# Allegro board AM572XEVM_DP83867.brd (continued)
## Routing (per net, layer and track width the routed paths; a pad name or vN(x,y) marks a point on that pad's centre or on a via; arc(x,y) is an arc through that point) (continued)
AM_CAP10: length 1.2
  TOP w0.12: U11.J16 v2(65.79,36.01)
  BOTTOM w0.254: C146.1 66.19,36.4 v2(65.79,36.01)
AM_CAP11: length 1.1
  TOP w0.12: U11.J10 v2(71.39,36.01)
  BOTTOM w0.254: C148.1 71.07,36.32 v2(71.39,36.01)
AM_CAP12: length 1.1
  TOP w0.12: U11.T20 v2(62.59,42.41)
  BOTTOM w0.254: v2(62.59,42.41) 62.9,42.09 C150.1
AM_CAP13: length 1.1
  TOP w0.12: U11.Y13 v2(68.99,45.61)
  BOTTOM w0.254: C152.1 68.67,45.29 v2(68.99,45.61)
AM_CAP14: length 2.5
  TOP w0.12: U11.K16 v2(66.59,37.61)
  BOTTOM w0.254: v2(66.59,37.61) 66.9,37.29 C154.1 67.56,36.54 R417.1
AUDIN_L: length 21.1
  TOP w0.102: v1(57.53,21.08) 57.67,20.94 U18.14
  INT_L3 w0.094: v1(44.83,12.7) 44.94,12.81 54.39,12.81 56.15,14.57 56.15,19.7 v1(57.53,21.08)
  BOTTOM w0.102: R230.1 v1(44.83,12.7)
AUDIN_R: length 21.2
  TOP w0.102: v1(56.77,21.08) 56.67,20.98 U18.16
  INT_L3 w0.094: v1(44.07,12.7) 44.58,13.21 54.23,13.21 55.75,14.73 55.75,19.8 56.77,20.81 v1(56.77,21.08)
  BOTTOM w0.102: R233.1 v1(44.07,12.7)
AUDIN_RL: length 1.6
  BOTTOM w0.12: C256.1 R233.2
AUDIN_RR: length 1.6
  BOTTOM w0.12: C255.1 R230.2
AUDIO_L: length 33.2
  TOP w0.102: U18.27 57.67,14.72 58.42,13.97 v1(58.42,13.72)
  BOTTOM w0.102: C250.1 32.26,12.7 31.93,13.03 31.93,13.39 33.55,15.01 50.53,15.01 52.81,12.73 57.05,12.73 58.04,13.72 v1(58.42,13.72)
AUDIO_R: length 33.1
  TOP w0.102: U18.29 58.67,14.48 v1(58.67,14.48)
  BOTTOM w0.102: v1(58.67,14.48) 58.3,14.48 56.9,13.08 52.96,13.08 50.67,15.37 33.41,15.37 31.57,13.53 31.57,13.03 31.24,12.7 C251.1
AUXFAN_EN: length 57.3
  TOP w0.12: U5.A12 v2(71.79,68.01)
  SIG_L5 w0.094: v1(81.41,58.39) 82.04,59.03 82.04,61.09 80.65,62.48 78.49,62.48 76.96,64.01 74.17,64.01 72.64,65.53 72.64,67.15 v2(71.79,68.01)
  BOTTOM w0.12: U32.1 110.49,50.8 109.86,51.44 85.34,51.44 82.3,54.48 82.3,57.51 v1(81.41,58.39) ; R24.1 74.84,67.98 74.68,67.82 71.98,67.82 v2(71.79,68.01)
B_UART3_RX: length 4.1
  TOP w0.12: U20.2 v1(27.3,37.08) 27.06,37.08 P10.4
  BOTTOM w0.12: R236.1 27.53,37.3 v1(27.3,37.08)
B_UART3_TX: length 2.8
  TOP w0.12: U20.3 27.06,36.58 P10.5
BATEN0: length 12.6
  TOP w0.12: v1(99.82,29.97) 99.06,30.73 99.06,34.54 98.26,35.34 R204.1 94.96,35.3 U17.36
  BOTTOM w0.12: v1(99.82,29.97) 100.08,29.72 100.08,28.56 100.2,28.44 U29.4
BATEN1: length 12
  TOP w0.12: v1(100.71,29.97) 100.33,29.59 100.33,29.58 100.21,29.46 99.57,29.46 98.81,30.23 98.81,34.42 98.17,35.05 95.58,35.05 95.46,34.93 U17.35
  BOTTOM w0.12: U29.5 100.71,28.99 v1(100.71,29.97)
BATEN2: length 4.8
  TOP w0.12: v1(97.16,34.54) 96.9,34.29 U17.33
  BOTTOM w0.12: U30.4 100.08,33.52 99.57,34.04 97.66,34.04 v1(97.16,34.54)
BATEN3: length 4.7
  TOP w0.12: U17.32 97.73,33.59 97.92,33.78 v1(97.92,34.54)
  BOTTOM w0.12: U30.5 100.22,34.02 99.7,34.54 v1(97.92,34.54)
BU_BATT: length 6.3
  TOP w0.12: BAT1.1 87.76,86.87 86.23,85.34 84.96,85.34 84.84,85.47 U6.3
  BOTTOM w0.12: R416.1 BAT1.1
CDC_CAP1: length 3
  TOP w0.12: C436.1 28.46,47.11 U7.19
CDC_CAP2: length 2.8
  TOP w0.12: C437.1 27.46,46.58 U7.17
CDC_OE: length 1.6
  TOP w0.12: U7.7 27.96,53.98 27.69,54.25 R313.1
CDC_OS1: length 5
  TOP w0.12: R310.2 R312.1 25.91,54.36 25.4,53.85 25.4,52.32 25.67,52.05 U7.10
CDC_OS2: length 4.1
  TOP w0.12: R311.1 R309.2 25.28,50.33 25.4,50.44 25.4,51.31 25.65,51.56 26.72,51.56 U7.11
CDC_OSCIN: length 3.4
  TOP w0.12: v1(29.97,47.5) 29.58,47.5 29.46,47.62 U7.21
  BOTTOM w0.12: Y8.3 29.97,46.35 v1(29.97,47.5) 30.01,47.53 C435.1
CLKOUT3: length 68.5
  TOP w0.12: U11.C23 v2(60.19,31.21)
  SIG_L5 w0.094: v1(29.21,32.13) 29.72,31.62 31.62,31.62 33.4,29.84 33.4,24.89 32.51,24 32.51,17.53 32.89,17.14 48.39,17.14 51.82,20.57 51.82,25.4 54.48,28.07 57.79,28.07 58.95,29.23 58.95,29.74 59.18,29.97 59.45,29.97 59.82,30.34 59.82,30.61 60.19,30.98 v2(60.19,31.21)
  BOTTOM w0.12: v1(29.21,32.13) 27.05,32.13 26.71,31.79 25.24,31.79 25.07,31.96 18.49,31.96 18.08,31.54 P17.41
CON.PCIE_RXN0: length 53.4
  TOP w0.12: U11.AG13 v3(68.99,51.21)
  BOTTOM w0.102: v3(68.99,51.21) 68.58,51.61 68.58,52.46 68.35,52.68 68.35,55.09 67.23,56.21 66.34,56.21 65.91,56.64 54.86,56.64 50.08,61.42 25.57,61.42 24.52,62.47 24.26,62.47 24.03,62.25 P19.25
CON.PCIE_RXN1: length 60.3
  TOP w0.12: U11.AG11 v3(70.59,51.21)
  BOTTOM w0.102: v3(70.59,51.21) 70.18,51.62 70.18,52.78 70.74,53.34 70.74,55.75 68.2,58.29 55.88,58.29 51.05,63.12 27.18,63.12 25.78,64.52 25.78,67.31 25.02,68.07 24.26,68.07 24.03,67.85 P19.18
CON.PCIE_RXP0: length 53.4
  TOP w0.12: U11.AH13 v3(68.99,52.01)
  BOTTOM w0.102: v3(68.99,52.01) 68.95,52.04 68.95,52.59 68.71,52.83 68.71,55.24 67.38,56.57 66.49,56.57 66.06,57 55.01,57 50.23,61.78 26.34,61.78 26.26,61.87 26.26,61.97 26.17,62.06 26.04,62.06 25.95,61.97 25.95,61.87 25.86,61.78 25.72,61.78 24.67,62.83 24.26,62.83 24.03,63.05 P19.24
CON.PCIE_RXP1: length 60.2
  TOP w0.12: U11.AH11 v3(70.59,52.01)
  BOTTOM w0.102: P19.17 24.06,68.65 24.28,68.43 25.17,68.43 26.14,67.46 26.14,64.66 26.3,64.5 26.42,64.5 26.49,64.57 26.62,64.57 26.71,64.48 26.71,64.35 26.64,64.29 26.64,64.16 27.33,63.47 51.2,63.47 56.03,58.65 68.35,58.65 71.09,55.9 71.09,53.19 70.53,52.63 70.53,52.06 v3(70.59,52.01)
CON.PCIE_TXN0: length 48
  BOTTOM w0.102: P19.28 24.03,59.85 24.26,60.07 24.77,60.07 25.27,60.58 49.66,60.58 54.36,55.88 65.71,55.88 66.06,55.52 66.65,55.52 67.08,55.1 67.08,54.35 C423.2
CON.PCIE_TXN1: length 52.5
  BOTTOM w0.102: P19.21 24.1,65.45 24.25,65.6 24.7,65.6 24.89,65.41 24.89,64.14 26.78,62.26 50.53,62.26 55.25,57.53 67.56,57.53 69.61,55.49 69.61,55.1 C425.2
CON.PCIE_TXP0: length 49.2
  BOTTOM w0.102: P19.27 24.03,60.65 24.26,60.43 24.62,60.43 24.78,60.59 24.78,60.72 24.59,60.91 24.59,61.04 24.68,61.13 24.8,61.13 25,60.93 49.81,60.93 54.5,56.24 65.85,56.24 66.21,55.88 66.8,55.88 67.44,55.24 67.44,54.32 C422.2
CON.PCIE_TXP1: length 53.2
  BOTTOM w0.102: C424.2 69.96,55.1 69.96,55.63 67.71,57.89 55.4,57.89 50.67,62.61 26.92,62.61 25.25,64.29 25.25,65.56 24.85,65.95 24.27,65.95 23.97,66.25 P19.20
CON_MMC1_CLK: length 22.6
  TOP w0.12: D21.3 69.61,13.62 R269.2 R262.2 67.83,12.29 69.39,10.72 v1(70.89,10.72)
  BOTTOM w0.12: v1(70.89,10.72) 70.89,11.25 70.46,11.68 69.6,11.68 69.19,11.28 69.19,10.24 69.82,9.6 69.82,8.46 70.1,8.18 70.89,8.18 71.27,7.8 71.27,6.93 71.12,6.78 70.66,6.78 70.56,6.68 70.56,6.4 70.69,6.27 71.15,6.27 71.27,6.15 71.27,5.89 71.15,5.77 70.36,5.77 70.15,5.56 70.15,5.33 70.38,5.11 70.71,5.11 70.92,4.9 P12.5
CON_MMC1_CMD: length 20.7
  TOP w0.12: D21.5 71.43,14.6 72.41,13.62 R267.2 R263.2 72.79,12.29 72.06,11.56 72.06,10.62 72.56,10.12 72.56,9.49 72.29,9.22 v1(69.22,9.22)
  BOTTOM w0.12: v1(69.22,9.22) 69.22,8.13 69.72,7.62 69.72,5.03 69.6,4.9 69.19,4.9 69.06,5.03 69.06,5.69 68.91,5.84 68.61,5.84 68.45,5.69 68.45,2.4 P12.3
CON_MMC1_DAT0: length 20.7
  TOP w0.12: R270.2 R261.2 66.47,12.29 66.04,11.85 66.04,10.19 66.2,10.02 D20.5 67,10.02 67.13,10.16 v1(71.37,10.16)
  BOTTOM w0.12: P12.7 73.12,4.13 71.83,5.41 71.83,5.69 72.09,5.94 72.62,5.94 72.82,6.15 72.82,6.45 72.59,6.68 72.03,6.68 71.83,6.88 71.83,8.1 71.37,8.56 70.82,8.56 70.51,8.86 70.51,9.86 70.82,10.16 v1(71.37,10.16)
CON_MMC1_DAT1: length 20.8
  TOP w0.12: R271.2 R260.2 65.21,12.27 65.1,12.27 64.69,11.86 64.69,9.22 64.89,9.03 D20.3 65.62,9.03 66.14,9.55 67.28,9.55 67.44,9.7 v1(71.91,9.7)
  BOTTOM w0.12: v1(71.91,9.7) 73.61,8 73.61,3.68 73.96,3.33 73.96,2.38 P12.8
CON_MMC1_DAT2: length 20.8
  TOP w0.12: v1(68.1,8.31) 74.24,8.31 74.78,8.84 74.78,9.38 D22.5 74.78,10.67 74.78,11.76 75.3,12.29 R265.2 R266.2
  BOTTOM w0.12: v1(68.1,8.31) 66.78,8.31 66.56,8.09 66.56,7.71 66.78,7.49 67.01,7.49 67.21,7.29 67.21,3.3 66.73,2.82 66.73,2.34 P12.1
CON_MMC1_DAT3: length 20.6
  TOP w0.12: v1(68.68,8.74) 73.79,8.74 D22.3 73.86,9.03 73.46,9.42 73.46,11.71 74.03,12.29 R264.2 R268.2
  BOTTOM w0.12: P12.2 67.62,2.9 67.77,3.05 67.77,5.97 68.05,6.25 69.06,6.25 69.22,6.4 69.22,6.58 69.06,6.73 68,6.73 67.77,6.96 67.77,7.59 67.92,7.75 68.38,7.75 68.68,8.05 v1(68.68,8.74)
CONN_SATA_RXN: length 7.8
  TOP w0.102: U33.12 79.24,87.37 v3(79.38,87.5)
  BOTTOM w0.102: v3(79.38,87.5) 79.38,87.71 79.45,87.78 79.45,93.12 79.16,93.41 79.16,93.97 C418.2
CONN_SATA_RXP: length 7.8
  TOP w0.102: v3(79.88,87.5) 79.74,87.36 U33.11
  BOTTOM w0.102: C420.2 79.51,93.97 79.51,93.56 79.81,93.27 79.81,87.78 79.88,87.71 v3(79.88,87.5)
CONN_SATA_TXN: length 1.4
  TOP w0.102: U33.14 78.24,87.37 v3(78.11,87.5)
  BOTTOM w0.102: C417.2 78.11,87.92 v3(78.11,87.5)
CONN_SATA_TXP: length 1.5
  TOP w0.102: U33.15 77.74,87.36 v3(77.6,87.5)
  BOTTOM w0.102: v3(77.6,87.5) 77.6,87.79 C416.1
CPU_NMIN: length 5.6
  TOP w0.12: U11.D21 v2(61.79,32.01)
  BOTTOM w0.12: R47.1 R46.2 60.33,29.08 60.59,29.34 60.59,31 61.6,32.01 v2(61.79,32.01)
CPU_POR_RESETN: length 81.7
  TOP w0.12: R53.2 v1(55.25,11.3)
  INT_L3 w0.094: v1(55.25,11.3) 56.26,11.3 57.02,12.06 60.02,12.06 63.25,8.84 65.18,8.84 66.45,10.11 68.68,10.11 69.67,11.1 69.67,11.13 70.61,12.06 75.31,12.06 77.47,14.22 77.47,24.38 78.99,25.91 78.99,45.72 78.66,46.05 78.41,46.05 77.34,47.12 77.34,47.37 77.09,47.62 76.84,47.62 76.58,47.88 76.58,49.15 75.82,49.91 75.82,59.56 76.82,60.57 v1(76.82,61.47) 76.33,61.96 v1(76.33,64.77)
  BOTTOM w0.12: v1(76.33,64.77) R41.2 ; U9.6 v1(76.82,61.47)
CPU_RESETN: length 83.5
  TOP w0.12: R55.1 v1(53.98,11.3)
  INT_L3 w0.094: v1(78.87,63.37) 78.74,63.25 78.74,60.96 79.25,60.45 79.25,58.67 78.74,58.17 78.74,52.58 79.5,51.82 79.5,48.77 79.99,48.28 79.99,31.35 79.25,30.61 79.25,25.65 77.72,24.13 77.72,13.97 75.56,11.81 71.04,11.81 69.01,9.78 66.8,9.78 65.51,8.48 62.99,8.48 59.66,11.81 57.28,11.81 56.26,10.79 54.48,10.79 v1(53.98,11.3)
  BOTTOM w0.12: R42.2 79.12,65.28 78.87,65.02 v1(78.87,63.37) 79.36,62.88 U10.1
DCAN1_RX: length 61.8
  TOP w0.12: U11.G19 v2(63.39,34.41)
  SIG_L10 w0.094: v2(63.39,34.41) 63.36,34.41 62.99,34.04 62.99,33.4 62.77,33.18 56.8,33.18 55.75,32.13 55.75,30.23 50.55,25.02 50.55,20.32 48.39,18.16 34.54,18.16 33.91,18.8 33.91,21.21 33.15,21.97 32.64,21.97 29.3,25.31 21.67,25.31 21.48,25.49 20.8,25.49 v1(20.45,25.14)
  BOTTOM w0.12: v1(20.45,25.14) 21.25,24.34 P17.20
DCAN1_TX: length 62.9
  TOP w0.12: U11.G20 v2(62.59,34.41)
  SIG_L10 w0.094: v2(62.59,34.41) 62.59,34.39 62.22,34.03 56.13,34.03 53.98,31.88 53.98,28.83 50.29,25.15 50.29,20.45 48.26,18.41 34.67,18.41 34.16,18.92 34.16,21.59 30.23,25.53 21.76,25.53 21.57,25.71 19.5,25.71 v1(18.92,25.14)
  BOTTOM w0.12: v1(18.92,25.14) 18.12,24.34 P17.50
DDR1_A0: length 51.4
  TOP w0.12: v2(37.78,47.21) U24.N3 ; v2(37.78,58.41) U23.N3 ; U11.AD20 v2(62.59,48.81)
  INT_L3 w0.094: v2(37.78,47.21) 37.38,47.61 37.38,54.65 38.61,55.88 38.61,57.09 37.78,57.91 v2(37.78,58.41)
  SIG_L5 w0.094: v2(62.59,48.81) 63,48.39 63.5,48.39 63.81,48.08 63.81,47.05 63.59,46.83 56.55,46.83 52.58,50.8 45.59,50.8 43.81,52.58 43.81,54.86 40.63,58.05 40.63,59.32 40.34,59.61 38.42,59.61 38.18,59.37 38.18,59.04 37.78,58.64 v2(37.78,58.41)
  BOTTOM w0.12: R364.1 v2(37.78,47.21)
DDR1_A1: length 51.4
  TOP w0.12: U11.AC19 v2(63.39,48.01) ; v2(36.98,43.21) U24.P7 ; v2(36.98,54.41) U23.P7
  SIG_L10 w0.094: v2(63.39,48.01) 63.39,48.23 63.76,48.61 63.76,51.43 63.61,51.58 63.23,51.58 62.99,51.82 62.99,53.21 58.55,57.66 38.1,57.66 36.45,56.01 36.45,54.94 v2(36.98,54.41) 36.58,54.01 36.58,52.52 37.03,52.07 37.03,49.66 36.58,49.21 36.58,46.81 37.03,46.35 37.03,44.39 36.58,43.94 36.58,43.61 v2(36.98,43.21)
  BOTTOM w0.12: R365.1 v2(36.98,43.21)
DDR1_A2: length 51.5
  TOP w0.12: U11.AC20 v2(62.59,48.01) ; v2(36.98,58.41) U23.P3 ; v2(36.98,47.21) U24.P3
  INT_L3 w0.094: v2(36.98,58.41) 36.98,57.91 37.85,57.05 37.85,55.88 36.58,54.62 36.58,47.61 v2(36.98,47.21)
  SIG_L5 w0.094: v2(36.98,58.41) 36.98,58.64 37.38,59.04 37.38,60.37 37.85,60.83 43.94,60.83 44.58,60.2 44.58,58.04 45.34,57.28 45.34,52.75 46.28,51.82 52.83,51.82 55.37,49.28 60.33,49.28 60.58,49.02 60.58,48.64 60.83,48.39 62.2,48.39 v2(62.59,48.01)
  BOTTOM w0.12: R371.1 v2(36.98,47.21)
DDR1_A3: length 51.9
  TOP w0.12: v2(37.78,59.21) U23.N2 ; v2(37.78,48.01) U24.N2 ; U11.AB19 v2(63.39,47.21)
  SIG_L5 w0.094: v2(63.39,47.21) 63.01,47.58 60.11,47.58 59.82,47.88 59.82,48.13 59.56,48.39 55.63,48.39 52.7,51.31 45.85,51.31 44.58,52.58 44.58,57.02 44.13,57.47 42.1,57.47 41.91,57.66 41.91,60.2 41.66,60.45 38.4,60.45 38.18,60.23 38.18,59.79 37.78,59.39 v2(37.78,59.21) 37.78,59.08 37.38,58.68 37.38,57.91 37.85,57.45 37.85,55.33 37.38,54.86 37.38,52.45 37.85,51.99 37.85,49.74 37.38,49.28 37.38,48.41 v2(37.78,48.01)
  BOTTOM w0.12: R376.1 38.18,49 38.18,48.41 v2(37.78,48.01)
DDR1_A4: length 52.1
  TOP w0.12: U11.AF21 v2(61.79,50.41) ; v2(36.98,42.41) U24.P8 ; v2(36.98,53.61) U23.P8
  SIG_L8 w0.094: v2(36.98,42.41) 36.58,42.81 36.58,43.69 37.08,44.19 37.08,46.23 36.58,46.74 36.58,49.28 37.08,49.78 37.08,51.82 36.58,52.32 36.58,53.21 v2(36.98,53.61) U23.P8 39.59,54.01 39.78,53.82 39.78,50.13 40.26,49.66 48.51,49.66 50.16,48.01 52.35,48.01 52.43,48.09 52.43,48.3 52.51,48.38 52.63,48.38 52.71,48.3 52.71,48.09 52.8,48.01 52.91,48.01 53,48.09 53,48.3 53.08,48.38 53.2,48.38 53.28,48.3 53.28,48.09 53.36,48.01 53.48,48.01 53.56,48.09 53.56,48.3 53.64,48.38 53.76,48.38 53.84,48.3 53.84,48.09 53.92,48.01 54.04,48.01 54.12,48.09 54.12,48.3 54.21,48.38 54.32,48.38 54.41,48.3 54.41,48.09 54.49,48.01 54.61,48.01 54.69,48.09 54.69,48.3 54.77,48.38 54.89,48.38 54.97,48.3 54.97,48.09 55.05,48.01 55.17,48.01 55.25,48.09 55.25,48.3 55.33,48.38 55.45,48.38 55.53,48.3 55.53,48.09 55.62,48.01 55.73,48.01 55.82,48.09 55.82,48.3 55.9,48.38 56.01,48.38 56.1,48.3 56.1,48.09 56.18,48.01 56.3,48.01 56.38,48.09 56.38,48.3 56.46,48.38 61.97,48.38 62.21,48.62 62.21,49.98 v2(61.79,50.41)
  BOTTOM w0.12: v2(36.98,42.41) 36.58,42.01 36.58,41.41 R366.1
DDR1_A5: length 52.2
  TOP w0.12: v2(36.98,48.01) U24.P2 ; U11.AH22 v2(60.99,52.01) ; v2(36.98,59.21) U23.P2
  SIG_L5 w0.094: v2(36.98,48.01) 36.58,48.41 36.58,49.28 37.08,49.78 37.08,51.95 36.58,52.45 36.58,54.86 37.08,55.37 37.08,57.41 36.58,57.91 36.58,58.68 36.98,59.08 v2(36.98,59.21)
  SIG_L8 w0.094: v2(60.99,52.01) 60.35,52.64 52.01,52.64 51.51,53.13 51.4,53.13 51.32,53.06 51.21,53.06 51.12,53.14 51.12,53.26 51.2,53.33 51.2,53.45 51.12,53.53 51,53.53 50.93,53.46 50.81,53.46 50.73,53.54 50.73,53.66 50.8,53.73 50.8,53.85 50.72,53.93 50.6,53.93 50.53,53.86 50.41,53.86 50.33,53.94 50.33,54.06 50.4,54.13 50.4,54.25 50.32,54.33 50.2,54.33 50.13,54.26 50.01,54.26 49.93,54.34 49.93,54.46 50,54.53 50,54.65 49.92,54.73 49.8,54.73 49.73,54.65 49.61,54.65 49.53,54.74 49.53,54.85 49.6,54.93 49.6,55.04 49.52,55.13 49.4,55.13 49.33,55.05 49.21,55.05 49.13,55.14 49.13,55.25 49.2,55.33 49.2,55.44 49.12,55.53 49.01,55.53 48.93,55.45 48.81,55.45 48.73,55.53 48.73,55.65 48.81,55.73 48.81,55.84 48.72,55.92 48.61,55.92 48.53,55.85 48.42,55.85 48.33,55.93 48.33,56.05 48.41,56.12 48.41,56.24 48.32,56.32 48.21,56.32 48.13,56.25 48.02,56.25 47.93,56.33 47.93,56.45 48.01,56.52 48.01,56.64 47.62,57.02 41.8,57.02 41.71,57.12 41.71,57.32 41.63,57.4 41.51,57.4 41.43,57.32 41.43,57.11 41.34,57.02 41.23,57.02 41.14,57.11 41.14,57.32 41.06,57.4 40.95,57.4 40.86,57.32 40.86,57.11 40.78,57.02 40.66,57.02 40.58,57.11 40.58,57.32 40.5,57.4 40.38,57.4 40.3,57.32 40.3,57.11 40.22,57.02 40.1,57.02 40.02,57.11 40.02,57.32 39.93,57.4 39.82,57.4 39.73,57.32 39.73,57.11 39.65,57.02 39.54,57.02 39.45,57.11 39.45,57.32 39.37,57.4 39.25,57.4 39.17,57.32 39.17,57.11 39.09,57.02 38.97,57.02 38.89,57.11 38.89,57.32 38.81,57.4 38.69,57.4 38.61,57.32 38.61,57.11 38.52,57.02 38.41,57.02 38.32,57.11 38.32,57.32 38.24,57.4 38.13,57.4 38.04,57.32 38.04,57.11 37.96,57.02 37.84,57.02 37.76,57.11 37.76,57.32 37.68,57.4 37.56,57.4 37.48,57.32 37.48,57.11 37.4,57.02 36.67,57.02 36.58,57.12 36.58,58.8 v2(36.98,59.21)
  BOTTOM w0.12: v2(36.98,48.01) 37.38,48.41 37.38,49 R367.1
DDR1_A6: length 52.6
  TOP w0.12: v2(36.18,53.61) U23.R8 ; U11.AG23 v2(60.19,51.21) ; v2(36.18,42.41) U24.R8
  SIG_L8 w0.094: v2(60.19,51.21) 60.43,51.21 60.83,50.8 61.21,50.8 61.36,50.65 61.36,50.19 61.2,50.03 57.45,50.03 57.08,49.66 56.97,49.66 56.88,49.74 56.88,49.96 56.8,50.04 56.68,50.04 56.6,49.96 56.6,49.74 56.52,49.66 56.4,49.66 56.32,49.74 56.32,49.96 56.24,50.04 56.12,50.04 56.04,49.96 56.04,49.74 55.96,49.66 55.84,49.66 55.76,49.74 55.76,49.96 55.67,50.04 55.56,50.04 55.47,49.96 55.47,49.74 55.39,49.66 55.27,49.66 55.19,49.74 55.19,49.96 55.11,50.04 54.99,50.04 54.91,49.96 54.91,49.74 54.83,49.66 54.71,49.66 54.63,49.74 54.63,49.96 54.55,50.04 54.43,50.04 54.35,49.96 54.35,49.74 54.26,49.66 49.53,49.66 48.77,50.42 41.66,50.42 41.4,50.67 41.4,54.86 41.02,55.24 36.2,55.24 35.78,54.83 35.78,54.01 v2(36.18,53.61) 35.78,53.21 35.78,52.32 36.32,51.78 36.32,49.82 35.78,49.28 35.78,46.74 36.2,46.32 36.2,44.1 35.78,43.69 35.78,42.81 v2(36.18,42.41)
  BOTTOM w0.12: v2(36.18,42.41) 35.78,42.01 35.78,41.41 R381.1
DDR1_A7: length 52.1
  TOP w0.12: v2(36.18,48.01) U24.R2 ; U11.AE21 v2(61.79,49.61) ; v2(36.18,59.21) U23.R2
  SIG_L5 w0.094: v2(61.79,49.61) 61.36,50.03 61.36,50.52 61.09,50.8 55.12,50.8 53.15,52.77 50.36,52.77 49.38,53.75 49.38,59.33 47.12,61.59 37.08,61.59 35.78,60.29 35.78,59.61 v2(36.18,59.21) 35.78,58.81 35.78,57.91 36.32,57.37 36.32,55.4 35.78,54.86 35.78,52.45 36.2,52.04 36.2,49.69 35.78,49.28 35.78,48.41 v2(36.18,48.01)
  BOTTOM w0.12: R369.1 36.58,49 36.58,48.41 v2(36.18,48.01)
DDR1_A8: length 52.4
  TOP w0.12: v2(35.38,42.41) U24.T8 ; v2(35.38,53.61) U23.T8 ; U11.AF22 v2(60.99,50.41)
  SIG_L8 w0.094: v2(60.99,50.41) 60.72,50.41 60.33,50.8 57.14,50.8 57.05,50.72 57.05,50.5 56.97,50.42 56.86,50.42 56.77,50.5 56.77,50.72 56.69,50.8 56.57,50.8 56.49,50.72 56.49,50.5 56.41,50.42 56.29,50.42 56.21,50.5 56.21,50.72 56.13,50.8 56.01,50.8 55.93,50.72 55.93,50.5 55.84,50.42 55.73,50.42 55.65,50.5 55.65,50.72 55.56,50.8 55.45,50.8 55.36,50.72 55.36,50.5 55.28,50.42 55.16,50.42 55.08,50.5 55.08,50.72 55,50.8 54.88,50.8 54.8,50.72 54.8,50.5 54.72,50.42 54.6,50.42 54.52,50.5 54.52,50.72 54.43,50.8 54.32,50.8 54.24,50.72 54.24,50.5 54.15,50.42 53.92,50.42 53.84,50.5 53.84,50.72 53.76,50.8 53.64,50.8 53.56,50.72 53.56,50.5 53.48,50.42 53.36,50.42 53.28,50.5 53.28,50.72 53.19,50.8 53.08,50.8 52.99,50.72 52.99,50.5 52.91,50.42 49.28,50.42 48.89,50.8 42.04,50.8 41.78,51.05 41.78,55.12 41.28,55.63 35.81,55.63 34.92,54.74 34.92,54.06 v2(35.38,53.61) 34.98,53.21 34.98,52.45 34.54,52.01 34.54,49.71 34.98,49.28 34.98,46.86 35.43,46.41 35.43,44.14 34.98,43.69 34.98,42.81 v2(35.38,42.41)
  BOTTOM w0.12: v2(35.38,42.41) 34.98,42.01 34.98,41.41 R383.1
DDR1_A9: length 50.9
  TOP w0.12: v2(36.18,47.21) U24.R3 ; v2(36.18,58.41) U23.R3 ; U11.AE22 v2(60.99,49.61)
  INT_L3 w0.094: v2(36.18,47.21) 35.78,47.61 35.78,54.58 37.08,55.88 37.08,57.01 36.18,57.91 v2(36.18,58.41)
  SIG_L5 w0.094: v2(60.99,49.61) 60.55,50.04 55.25,50.04 52.96,52.32 47.18,52.32 47.01,52.5 47.01,60.18 45.97,61.21 37.21,61.21 36.58,60.59 36.58,59.04 36.18,58.64 v2(36.18,58.41)
  BOTTOM w0.12: R368.1 v2(36.18,47.21)
DDR1_A10: length 51.2
  TOP w0.12: v2(39.38,54.41) U23.L7 ; U11.AD21 v2(61.79,48.81) ; v2(39.38,43.21) U24.L7
  SIG_L10 w0.094: v2(61.79,48.81) 61.36,49.23 61.36,51.36 61.14,51.58 60.69,51.58 60.58,51.69 60.58,53.21 60.33,53.47 59.18,53.47 58.55,54.1 58.55,55.63 57.91,56.27 56.94,56.27 56.85,56.18 56.85,55.96 56.77,55.88 56.65,55.88 56.57,55.96 56.57,56.18 56.49,56.27 56.37,56.27 56.29,56.18 56.29,55.96 56.21,55.88 56.09,55.88 56.01,55.96 56.01,56.18 55.92,56.27 55.81,56.27 55.73,56.18 55.73,55.96 55.64,55.88 55.53,55.88 55.44,55.96 55.44,56.18 55.36,56.27 55.24,56.27 55.16,56.18 55.16,55.96 55.08,55.88 54.96,55.88 54.88,55.96 54.88,56.18 54.8,56.27 54.68,56.27 54.6,56.18 54.6,55.96 54.52,55.88 54.4,55.88 54.32,55.96 54.32,56.18 54.23,56.27 54.12,56.27 54.03,56.18 54.03,55.96 53.95,55.88 53.83,55.88 53.75,55.96 53.75,56.18 53.67,56.27 53.55,56.27 53.47,56.18 53.47,55.96 53.39,55.88 53.27,55.88 53.19,55.96 53.19,56.18 53.11,56.27 52.99,56.27 52.91,56.18 52.91,55.96 52.82,55.88 52.71,55.88 52.62,55.96 52.62,56.18 52.54,56.27 52.42,56.27 52.34,56.18 52.34,55.96 52.26,55.88 52.14,55.88 52.06,55.96 52.06,56.18 51.98,56.27 51.86,56.27 51.78,56.18 51.78,55.96 51.7,55.88 51.58,55.88 51.5,55.96 51.5,56.18 51.41,56.27 51.3,56.27 51.21,56.18 51.21,55.96 51.13,55.88 51.02,55.88 50.93,55.96 50.93,56.18 50.43,56.69 40.56,56.69 39.38,55.51 v2(39.38,54.41) 38.98,54.01 38.98,52.52 39.43,52.07 39.43,49.66 38.98,49.21 38.98,46.81 39.43,46.35 39.43,44.39 38.98,43.94 38.98,43.61 v2(39.38,43.21)
  BOTTOM w0.12: R373.1 v2(39.38,43.21)
DDR1_A11: length 50.7
  TOP w0.12: v2(36.18,43.21) U24.R7 ; v2(36.18,54.41) U23.R7 ; U11.AD22 v2(60.99,48.81)
  SIG_L8 w0.094: v2(60.99,48.81) 60.56,49.23 57.29,49.23 57.21,49.15 57.21,48.98 57.12,48.9 57.01,48.9 56.92,48.98 56.92,49.15 56.84,49.23 56.72,49.23 56.64,49.15 56.64,48.98 56.56,48.9 56.44,48.9 56.36,48.98 56.36,49.15 56.28,49.23 56.16,49.23 56.08,49.15 56.08,48.98 56,48.9 55.88,48.9 55.8,48.98 55.8,49.15 55.71,49.23 55.6,49.23 55.51,49.15 55.51,48.98 55.43,48.9 55.32,48.9 55.23,48.98 55.23,49.15 55.15,49.23 55.03,49.23 54.95,49.15 54.95,48.98 54.87,48.9 54.75,48.9 54.67,48.98 54.67,49.15 54.59,49.23 54.47,49.23 54.39,49.15 54.39,48.98 54.3,48.9 54.19,48.9 54.1,48.98 54.1,49.15 54.02,49.23 53.91,49.23 53.82,49.15 53.82,48.98 53.74,48.9 53.62,48.9 53.54,48.98 53.54,49.15 53.46,49.23 53.34,49.23 53.26,49.15 53.26,48.98 53.18,48.9 53.06,48.9 52.98,48.98 52.98,49.15 52.89,49.23 52.78,49.23 52.7,49.15 52.7,48.98 52.61,48.9 52.5,48.9 52.41,48.98 52.41,49.15 52.33,49.23 52.21,49.23 52.13,49.15 52.13,48.98 52.05,48.9 51.93,48.9 51.85,48.98 51.85,49.15 51.77,49.23 51.65,49.23 51.57,49.15 51.57,48.98 51.48,48.9 51.37,48.9 51.29,48.98 51.29,49.15 51.2,49.23 51.09,49.23 51,49.15 51,48.98 50.92,48.9 50.8,48.9 50.72,48.98 50.72,49.15 50.64,49.23 50.52,49.23 50.44,49.15 50.44,48.98 50.36,48.9 49.78,48.9 48.64,50.04 40.77,50.04 40.58,50.22 40.58,51.09 40.59,51.09 40.59,51.43 40.58,51.43 40.58,54.67 40.39,54.86 36.64,54.86 v2(36.18,54.41)
  SIG_L10 w0.094: v2(36.18,54.41) 35.78,54.01 35.78,52.52 36.23,52.07 36.23,49.66 35.78,49.21 35.78,46.81 36.23,46.35 36.23,44.39 35.78,43.94 35.78,43.61 v2(36.18,43.21)
  BOTTOM w0.12: R380.1 v2(36.18,43.21)
DDR1_A12: length 51.1
  TOP w0.12: U11.AC21 v2(61.79,48.01) ; v2(37.78,43.21) U24.N7 ; v2(37.78,54.41) U23.N7
  SIG_L10 w0.094: v2(61.79,48.01) 62.05,48.01 62.48,48.43 62.78,48.43 62.99,48.64 62.99,51.36 62.72,51.63 62.42,51.63 62.21,51.84 62.21,53.11 61.09,54.23 59.63,54.23 59.29,54.57 59.29,56.03 57.98,57.34 38.41,57.34 37.21,56.13 37.21,54.98 v2(37.78,54.41) 37.38,54.01 37.38,52.52 37.83,52.07 37.83,49.66 37.38,49.21 37.38,46.81 37.83,46.35 37.83,44.39 37.38,43.94 37.38,43.61 v2(37.78,43.21)
  BOTTOM w0.12: R379.1 v2(37.78,43.21)
DDR1_A13: length 51.1
  TOP w0.12: v2(35.38,47.21) U24.T3 ; U11.AF18 v2(64.19,50.41) ; v2(35.38,58.41) U23.T3
  INT_L3 w0.094: v2(64.19,50.41) 63.79,50.8 63.18,50.8 62.96,51.02 62.96,51.36 62.7,51.63 62.43,51.63 62.16,51.89 62.16,52.39 59.18,55.37 58.8,55.37 52.07,62.1 37.72,62.1 35.78,60.17 35.78,58.81 v2(35.38,58.41) 35.38,57.96 36.32,57.02 36.32,55.91 34.98,54.57 34.98,47.61 v2(35.38,47.21)
  BOTTOM w0.12: R370.1 v2(35.38,47.21)
DDR1_A14: length 51.1
  TOP w0.12: U11.AE17 v2(64.99,49.61) ; v2(35.38,43.21) U24.T7 ; v2(35.38,54.41) U23.T7
  SIG_L10 w0.094: v2(35.38,43.21) 34.98,43.61 34.98,43.94 35.43,44.39 35.43,46.35 34.98,46.81 34.98,49.21 34.54,49.64 34.54,52.08 34.98,52.52 34.98,54.01 v2(35.38,54.41) 35.38,55.45 37.97,58.04 58.8,58.04 64.56,52.28 64.56,50.03 v2(64.99,49.61)
  BOTTOM w0.12: R382.1 v2(35.38,43.21)
DDR1_A15: length 51.4
  TOP w0.12: U11.AD18 v2(64.19,48.81) ; v2(38.58,54.41) U23.M7 ; v2(38.58,43.21) U24.M7
  SIG_L10 w0.094: v2(38.58,43.21) 38.18,43.61 38.18,43.94 38.63,44.39 38.63,46.35 38.18,46.81 38.18,49.21 38.63,49.66 38.63,52.07 38.18,52.52 38.18,54.01 v2(38.58,54.41) 38.58,55.35 40.25,57.01 57.67,57.01 58.93,55.75 58.93,54.36 59.44,53.85 60.58,53.85 61.36,53.06 61.36,51.82 61.6,51.58 61.96,51.58 62.17,51.37 62.17,48.61 61.94,48.39 61.63,48.39 61.41,48.16 61.41,47.81 61.59,47.62 63.62,47.62 63.81,47.82 63.81,48.16 64.19,48.54 v2(64.19,48.81)
  BOTTOM w0.12: R375.1 v2(38.58,43.21)
DDR1_BA0: length 52.3
  TOP w0.12: v2(38.58,48.01) U24.M2 ; U11.AF17 v2(64.99,50.41) ; v2(38.58,59.21) U23.M2
  SIG_L5 w0.094: v2(38.58,48.01) 38.18,48.41 38.18,49.28 38.61,49.7 38.61,51.94 38.18,52.37 38.18,54.86 38.61,55.29 38.61,57.49 38.18,57.91 38.18,58.68 38.58,59.08 v2(38.58,59.21)
  SIG_L8 w0.094: v2(38.58,59.21) 38.98,59.61 48.6,59.61 48.69,59.51 48.69,59.4 48.55,59.26 48.55,59.14 48.64,59.06 48.75,59.06 48.89,59.2 49.01,59.2 49.09,59.11 49.09,59 48.95,58.86 48.95,58.74 49.03,58.66 49.15,58.66 49.29,58.8 49.41,58.8 49.49,58.72 49.49,58.6 49.35,58.46 49.35,58.35 49.43,58.26 49.55,58.26 49.69,58.4 49.8,58.4 49.89,58.32 49.89,58.2 49.75,58.06 49.75,57.95 49.83,57.86 49.95,57.86 50.09,58 50.2,58 50.29,57.92 50.29,57.8 50.15,57.66 50.15,57.55 50.23,57.47 50.35,57.47 50.48,57.6 50.6,57.6 50.68,57.52 50.68,57.4 50.55,57.27 50.55,57.15 50.63,57.07 50.75,57.07 50.88,57.2 51,57.2 51.08,57.12 51.08,57 50.95,56.87 50.95,56.75 51.03,56.67 51.15,56.67 51.28,56.8 51.4,56.8 51.48,56.72 51.48,56.61 51.34,56.47 51.34,56.35 51.43,56.27 51.54,56.27 51.68,56.41 51.8,56.41 51.88,56.32 51.88,56.21 51.74,56.07 51.74,55.95 51.83,55.87 51.94,55.87 52.08,56.01 52.2,56.01 52.28,55.92 52.28,55.81 52.14,55.67 52.14,55.55 52.22,55.47 52.34,55.47 52.48,55.61 52.6,55.61 52.68,55.53 52.68,55.41 52.54,55.27 52.54,55.16 52.62,55.07 52.74,55.07 52.88,55.21 52.99,55.21 54.28,53.93 62.02,53.93 63.76,52.19 63.76,51.89 64.08,51.58 64.34,51.58 64.56,51.36 64.56,51.09 64.99,50.67 v2(64.99,50.41)
  BOTTOM w0.12: v2(38.58,48.01) 38.98,48.41 38.98,49 R363.1
DDR1_BA1: length 52.1
  TOP w0.12: v2(37.78,42.41) U24.N8 ; v2(37.78,53.61) U23.N8 ; U11.AE18 v2(64.19,49.61)
  SIG_L8 w0.094: v2(64.19,49.61) 63.76,49.18 63.76,48.65 63.5,48.38 63.23,48.38 63.01,48.16 63.01,47.92 62.96,47.88 62.96,47.85 62.74,47.63 56.43,47.63 56.35,47.55 56.35,47.33 56.27,47.24 56.15,47.24 56.07,47.33 56.07,47.55 55.98,47.63 55.87,47.63 55.79,47.55 55.79,47.33 55.7,47.24 55.59,47.24 55.5,47.33 55.5,47.55 55.42,47.63 55.3,47.63 55.22,47.55 55.22,47.33 55.14,47.24 55.02,47.24 54.94,47.33 54.94,47.55 54.86,47.63 54.74,47.63 54.66,47.55 54.66,47.33 54.57,47.24 54.46,47.24 54.38,47.33 54.38,47.55 54.29,47.63 54.18,47.63 54.09,47.55 54.09,47.33 54.01,47.24 53.89,47.24 53.81,47.33 53.81,47.55 53.73,47.63 53.61,47.63 53.53,47.55 53.53,47.33 53.45,47.24 53.33,47.24 53.25,47.33 53.25,47.55 53.17,47.63 53.05,47.63 52.97,47.55 52.97,47.33 52.88,47.24 52.77,47.24 52.68,47.33 52.68,47.55 52.6,47.63 52.48,47.63 52.4,47.55 52.4,47.33 52.32,47.24 50.42,47.24 48.39,49.28 39.75,49.28 38.98,50.04 38.98,52.97 38.75,53.21 38.18,53.21 v2(37.78,53.61) 37.38,53.21 37.38,52.32 37.85,51.86 37.85,49.74 37.38,49.28 37.38,46.74 37.85,46.27 37.85,44.15 37.38,43.69 37.38,42.81 v2(37.78,42.41)
  BOTTOM w0.12: v2(37.78,42.41) 37.38,42.01 37.38,41.41 R377.1
DDR1_BA2: length 50.8
  TOP w0.12: v2(38.58,47.21) U24.M3 ; v2(38.58,58.41) U23.M3 ; U11.AB18 v2(64.19,47.21)
  INT_L3 w0.094: v2(38.58,47.21) 38.18,47.61 38.18,54.69 39.37,55.88 39.37,57.12 38.58,57.91 v2(38.58,58.41)
  SIG_L8 w0.094: v2(38.58,58.41) 38.82,58.41 39.22,58.81 43.06,58.81 43.14,58.72 43.14,58.63 43.22,58.55 43.34,58.55 43.42,58.63 43.42,58.72 43.51,58.81 43.62,58.81 43.71,58.72 43.71,58.63 43.79,58.55 43.91,58.55 43.99,58.63 43.99,58.72 44.07,58.81 48.38,58.81 52.65,54.54 52.76,54.54 52.9,54.68 53.02,54.68 53.1,54.59 53.1,54.48 52.96,54.34 52.96,54.22 53.05,54.14 53.16,54.14 53.3,54.28 53.42,54.28 53.5,54.2 53.5,54.08 53.36,53.94 53.36,53.83 53.58,53.6 61.71,53.6 63.01,52.31 63.01,51.85 63.23,51.63 63.54,51.63 63.81,51.36 63.81,51.05 64.03,50.83 64.34,50.83 64.61,50.56 64.61,50.21 64.83,49.98 65.14,49.98 65.41,49.72 65.41,48.69 65.14,48.43 64.81,48.43 64.61,48.23 64.61,47.72 64.19,47.3 v2(64.19,47.21)
  BOTTOM w0.12: R378.1 v2(38.58,47.21)
DDR1_CASN: length 51
  TOP w0.12: v2(40.18,58.41) U23.K3 ; v2(40.18,47.21) U24.K3 ; U11.AC18 v2(64.19,48.01)
  INT_L3 w0.094: v2(40.18,47.21) 39.78,47.61 39.78,49.31 41.02,50.55 41.02,52.2 40.58,52.64 40.58,54.74 40.89,55.05 40.89,57.4 40.18,58.12 v2(40.18,58.41)
  SIG_L8 w0.094: v2(40.18,58.41) 40.55,58.04 48.64,58.04 48.8,57.88 48.8,57.77 48.66,57.63 48.66,57.51 48.74,57.43 48.86,57.43 49,57.57 49.11,57.57 49.2,57.48 49.2,57.37 49.06,57.23 49.06,57.11 49.14,57.03 49.26,57.03 49.4,57.17 49.51,57.17 49.59,57.09 49.59,56.97 49.46,56.83 49.46,56.71 49.54,56.63 49.66,56.63 49.79,56.77 49.91,56.77 49.99,56.69 49.99,56.57 49.86,56.43 49.86,56.32 49.94,56.23 50.06,56.23 50.19,56.37 50.31,56.37 50.39,56.29 50.39,56.17 50.25,56.03 50.25,55.92 50.34,55.83 50.45,55.83 50.59,55.97 50.71,55.97 50.79,55.89 50.79,55.77 50.65,55.64 50.65,55.52 50.74,55.44 50.85,55.44 50.99,55.57 51.11,55.57 51.19,55.49 51.19,55.37 51.05,55.24 51.05,55.12 51.13,55.04 51.25,55.04 51.39,55.17 51.51,55.17 51.59,55.09 51.59,54.97 51.45,54.84 51.45,54.72 51.53,54.64 51.65,54.64 51.79,54.78 51.9,54.78 51.99,54.69 51.99,54.58 51.85,54.44 51.85,54.32 51.93,54.24 52.05,54.24 52.19,54.38 52.3,54.38 52.39,54.29 52.39,54.18 52.25,54.04 52.25,53.92 52.33,53.84 52.45,53.84 52.59,53.98 52.7,53.98 52.78,53.9 52.78,53.78 52.65,53.64 52.65,53.52 52.73,53.44 52.85,53.44 52.98,53.58 53.1,53.58 53.4,53.28 61.4,53.28 62.21,52.47 62.21,51.85 62.43,51.63 62.7,51.63 63.01,51.32 63.01,51.05 64.03,50.03 64.3,50.03 64.56,49.76 64.56,48.64 64.26,48.34 64.26,48.26 64.19,48.18 v2(64.19,48.01)
  BOTTOM w0.12: R361.1 v2(40.18,47.21)
DDR1_CKE: length 53.2
  TOP w0.12: v2(40.18,41.61) U24.K9 ; v2(40.18,52.81) U23.K9 ; U11.AG22 v2(60.99,51.21)
  SIG_L10 w0.094: v2(60.99,51.21) 60.98,51.21 60.58,50.8 60.06,50.8 59.76,51.09 59.76,52.89 59.56,53.09 58.93,53.09 58.17,53.85 58.17,55.05 58.07,55.14 56.4,55.14 56.32,55.22 56.32,55.41 56.23,55.5 56.12,55.5 56.04,55.42 56.04,55.22 55.96,55.14 55.84,55.14 55.76,55.22 55.76,55.42 55.67,55.5 55.56,55.5 55.47,55.42 55.47,55.22 55.39,55.14 55.27,55.14 55.19,55.22 55.19,55.42 55.11,55.5 54.99,55.5 54.91,55.42 54.91,55.22 54.83,55.14 54.71,55.14 54.63,55.22 54.63,55.42 54.55,55.5 54.43,55.5 54.35,55.42 54.35,55.22 54.26,55.14 54.15,55.14 54.06,55.22 54.06,55.42 53.98,55.5 53.86,55.5 53.78,55.42 53.78,55.1 53.7,55.01 53.58,55.01 53.5,55.1 53.5,55.42 53.42,55.5 53.3,55.5 53.22,55.42 53.22,55.1 53.14,55.01 53.02,55.01 52.94,55.1 52.94,55.42 52.85,55.5 52.74,55.5 52.65,55.42 52.65,55.1 52.57,55.01 52.46,55.01 52.37,55.1 52.37,55.42 52.29,55.5 52.17,55.5 52.09,55.42 52.09,55.1 52.01,55.01 51.89,55.01 51.81,55.1 51.81,55.42 51.73,55.5 51.61,55.5 51.53,55.42 51.53,55.1 51.44,55.01 51.33,55.01 51.24,55.1 51.24,55.42 51.16,55.5 51.05,55.5 50.96,55.42 50.96,55.1 50.88,55.01 50.76,55.01 50.68,55.1 50.68,55.42 50.6,55.5 50.48,55.5 50.4,55.42 50.4,55.1 50.32,55.01 50.2,55.01 50.12,55.1 50.12,55.42 50.03,55.5 49.92,55.5 49.84,55.42 49.84,55.13 49.74,55.04 49.61,55.04 48.89,55.75 40.39,55.75 39.78,55.15 39.78,53.18 40.16,52.81 v2(40.18,52.81) 39.78,52.41 39.78,50.93 40.26,50.45 40.26,49.63 39.78,49.15 39.78,46.74 40.13,46.39 40.13,44.29 39.78,43.94 39.78,42.01 v2(40.18,41.61)
  BOTTOM w0.12: R282.1 40.58,41.21 v2(40.18,41.61) ; R333.1 60.59,52.35 60.59,51.61 v2(60.99,51.21)
DDR1_CLK0: length 51.2
  TOP w0.12: v2(40.98,54.41) U23.J7 ; U11.AG24 v2(59.39,51.21) ; v2(40.98,43.21) U24.J7
  SIG_L10 w0.094: v2(40.98,43.21) 40.68,43.21 40.58,43.3 40.58,43.57 41.8,44.79 41.8,53.92 41.55,54.17 41.31,54.41 41.15,54.41 41.15,54.41 v2(40.98,54.41) 40.82,54.41 40.68,54.54 40.68,54.67 40.88,54.86 48.64,54.86 49.68,53.83 49.68,51.88 49.99,51.56 50.57,51.56 50.88,51.88 50.88,53.62 50.97,53.7 51.21,53.7 51.29,53.62 51.29,51.88 51.61,51.56 52.18,51.56 52.5,51.88 52.5,53.62 52.58,53.7 52.83,53.7 52.91,53.62 52.91,51.88 53.22,51.56 53.8,51.56 54.11,51.88 54.11,53.62 54.2,53.7 54.44,53.7 54.52,53.62 54.52,51.88 54.84,51.56 55.41,51.56 55.73,51.88 55.73,53.62 55.81,53.7 56.6,53.7 58.7,51.61 59.26,51.61 59.39,51.48 v2(59.39,51.21)
  BOTTOM w0.12: R284.1 v2(40.98,43.21)
DDR1_CLK0N: length 51.3
  TOP w0.12: U11.AH24 v2(59.39,52.01) ; v2(40.18,43.21) U24.K7 ; v2(40.18,54.41) U23.K7
  SIG_L10 w0.094: v2(59.39,52.01) 58.87,52.01 56.77,54.1 55.65,54.1 55.33,53.79 55.33,52.04 55.25,51.96 55,51.96 54.92,52.04 54.92,53.79 54.61,54.1 54.03,54.1 53.72,53.79 53.72,52.04 53.63,51.96 53.39,51.96 53.31,52.04 53.31,53.79 52.99,54.1 52.42,54.1 52.1,53.79 52.1,52.04 52.02,51.96 51.77,51.96 51.69,52.04 51.69,53.79 51.38,54.1 50.8,54.1 50.48,53.79 50.48,52.04 50.4,51.96 50.16,51.96 50.08,52.04 50.08,53.94 48.75,55.26 40.71,55.26 40.18,54.73 v2(40.18,54.41) 40.58,54.01 40.63,54.01 40.64,54.01 40.82,54.01 40.82,54.01 41.15,54.01 41.4,53.75 41.4,44.96 40.18,43.74 v2(40.18,43.21)
  BOTTOM w0.12: R283.1 v2(40.18,43.21)
DDR1_CLK_TERM: length 1.6
  BOTTOM w0.12: R283.2 R284.2 C388.2
DDR1_CSN0: length 52.4
  TOP w0.12: U11.AH23 v2(60.19,52.01) ; v2(39.38,48.01) U24.L2 ; v2(39.38,59.21) U23.L2
  SIG_L5 w0.094: v2(39.38,48.01) 38.98,48.41 38.98,49.28 39.37,49.66 39.37,52.07 38.98,52.46 38.98,54.86 39.37,55.25 39.37,57.52 38.98,57.91 38.98,58.81 v2(39.38,59.21)
  SIG_L8 w0.094: v2(60.19,52.01) 59.88,52.31 51.45,52.31 51.23,52.53 51.11,52.53 51.04,52.46 50.92,52.46 50.84,52.54 50.84,52.65 50.91,52.73 50.91,52.84 50.83,52.93 50.71,52.93 50.64,52.85 50.52,52.85 50.44,52.94 50.44,53.05 50.52,53.13 50.52,53.24 50.43,53.33 50.32,53.33 50.24,53.25 50.13,53.25 50.04,53.34 50.04,53.45 50.12,53.53 50.12,53.64 50.03,53.72 49.92,53.72 49.84,53.65 49.73,53.65 49.64,53.73 49.64,53.85 49.72,53.92 49.72,54.04 49.64,54.12 49.52,54.12 49.44,54.05 49.33,54.05 49.25,54.13 49.25,54.25 49.32,54.32 49.32,54.44 49.24,54.52 49.12,54.52 49.05,54.45 48.93,54.45 48.85,54.53 48.85,54.65 48.92,54.72 48.92,54.84 48.84,54.92 48.72,54.92 48.65,54.85 48.53,54.85 48.45,54.93 48.45,55.05 48.52,55.12 48.52,55.24 48.44,55.32 48.32,55.32 48.25,55.25 48.13,55.25 48.05,55.33 48.05,55.45 48.12,55.52 48.12,55.64 48.04,55.72 47.92,55.72 47.85,55.64 47.73,55.64 47.65,55.73 47.65,55.84 47.72,55.92 47.72,56.03 47.64,56.12 47.52,56.12 47.45,56.04 47.33,56.04 47.25,56.13 47.25,56.24 47.33,56.32 47.33,56.43 47.12,56.64 35.91,56.64 35.81,56.74 35.81,59.44 35.99,59.61 37.95,59.61 38.18,59.37 38.18,59.04 38.42,58.81 38.75,58.81 38.98,59.04 38.98,59.05 39.14,59.21 v2(39.38,59.21)
  BOTTOM w0.12: R362.1 39.78,49 39.78,48.41 v2(39.38,48.01)
DDR1_D0: length 23.9
  TOP w0.12: v2(44.98,58.41) U23.E3 ; U11.AF25 v2(58.59,50.41)
  BOTTOM w0.12: v2(44.98,58.41) 43.55,58.41 43.43,58.29 43.43,57.4 43.55,57.28 43.79,57.28 43.9,57.38 43.9,57.68 44,57.78 44.15,57.78 44.26,57.68 44.26,57.38 44.36,57.28 44.51,57.28 44.62,57.38 44.62,57.68 44.72,57.78 44.87,57.78 44.98,57.68 44.98,57.51 45.08,57.4 51.31,57.4 55.37,53.34 55.37,52.7 55.63,52.45 57.28,52.45 57.79,51.94 57.79,51.21 v2(58.59,50.41)
DDR1_D1: length 24.1
  TOP w0.12: U11.AF26 v2(57.79,50.41) ; v2(42.58,58.41) U23.H3
  BOTTOM w0.12: v2(57.79,50.41) 57.67,50.29 57.15,50.29 56.77,49.91 55.12,49.91 54.86,50.16 54.86,53.09 51.05,56.9 45.72,56.9 44.96,56.13 42.55,56.13 42.16,56.52 42.16,57.99 v2(42.58,58.41)
DDR1_D2: length 24.3
  TOP w0.12: U11.AG26 57.79,51.21 57.79,51.44 57.79,51.44 57.79,51.77 57.79,51.77 57.79,51.82 57.15,52.45 55.75,52.45 54.23,53.98 54.23,57.4 53.98,57.66 53.31,57.66 53.2,57.76 53.2,57.93 53.1,58.04 52.95,58.04 52.84,57.93 52.84,57.76 52.74,57.66 52.59,57.66 52.49,57.76 52.49,57.93 52.38,58.04 52.23,58.04 52.13,57.93 52.13,57.76 52.02,57.66 51.87,57.66 51.77,57.76 51.77,57.93 51.66,58.04 51.51,58.04 51.41,57.93 51.41,57.76 51.3,57.66 51.15,57.66 51.05,57.76 51.05,57.93 50.94,58.04 50.79,58.04 50.69,57.93 50.69,57.76 50.58,57.66 49.72,57.66 48.7,56.64 44.58,56.64 44.18,56.25 44.18,54.47 43.78,54.07 U23.F8
DDR1_D3: length 24.1
  TOP w0.12: U23.F7 43.78,56.36 44.45,57.02 48.51,57.02 49.91,58.42 50.65,58.42 50.76,58.53 50.76,58.7 50.86,58.8 51.01,58.8 51.11,58.7 51.11,58.53 51.22,58.42 51.37,58.42 51.47,58.53 51.47,58.7 51.58,58.8 51.73,58.8 51.83,58.7 51.83,58.53 51.94,58.42 52.09,58.42 52.19,58.53 52.19,58.7 52.3,58.8 52.45,58.8 52.55,58.7 52.55,58.53 52.66,58.42 52.81,58.42 52.91,58.53 52.91,58.7 53.02,58.8 53.17,58.8 53.27,58.7 53.27,58.53 53.38,58.42 54.1,58.42 54.61,57.91 54.61,54.1 55.86,52.85 57.26,52.85 58.19,51.92 U11.AH26
DDR1_D4: length 24
  TOP w0.12: v2(43.38,59.21) U23.G2 ; U11.AF24 v2(59.39,50.41)
  INT_L3 w0.094: v2(43.38,59.21) 43.08,59.21 42.93,59.06 42.93,58.28 43.08,58.14 44.44,58.14 44.63,58.33 44.63,59.36 44.92,59.66 48.93,59.66 55.5,53.09 56.3,53.09 57.69,51.69 57.91,51.69 59.2,50.41 v2(59.39,50.41)
DDR1_D5: length 23.6
  TOP w0.12: v2(42.58,54.41) U23.H7 ; U11.AE24 v2(59.39,49.61)
  BOTTOM w0.12: v2(42.58,54.41) 42.58,55.41 42.8,55.63 51.56,55.63 54.36,52.83 54.36,49.91 54.74,49.53 56.9,49.53 57.37,50.01 58.2,50.01 58.6,49.61 v2(59.39,49.61)
DDR1_D6: length 24.3
  TOP w0.12: v2(44.18,59.21) U23.F2 ; U11.AF23 v2(60.19,50.41)
  INT_L3 w0.094: v2(44.18,59.21) 43.78,59.61 43.26,59.61 43.03,59.84 43.03,60.18 43.31,60.45 48.64,60.45 55.63,53.47 56.37,53.47 57.51,52.32 57.86,52.32 59.4,50.78 59.71,50.78 60.08,50.41 v2(60.19,50.41)
DDR1_D7: length 23.9
  TOP w0.12: v2(42.58,53.61) U23.H8 ; U11.AE23 v2(60.19,49.61)
  SIG_L10 w0.094: v2(42.58,53.61) 42.93,53.25 42.93,52.7 43.69,51.94 47.62,51.94 51.94,47.62 60.33,47.62 60.58,47.88 60.58,49.21 v2(60.19,49.61)
DDR1_D8: length 21.5
  TOP w0.12: U11.AC23 v2(60.19,48.01) ; v2(45.78,54.41) U23.D7
  INT_L3 w0.094: v2(60.19,48.01) 59.76,47.58 56.18,47.58 48.01,55.75 45.09,55.75 44.96,55.63 44.96,55.23 v2(45.78,54.41)
DDR1_D9: length 21.4
  TOP w0.12: v2(46.61,56.23) 48.86,56.23 49.78,57.15 52.04,57.15 52.15,57.04 52.15,56.62 52.25,56.52 52.4,56.52 52.51,56.62 52.51,57.04 52.61,57.15 52.76,57.15 52.87,57.04 52.87,56.62 52.97,56.52 53.12,56.52 53.23,56.62 53.23,57.04 53.33,57.15 53.73,57.15 53.85,57.03 53.85,52.83 56.27,50.41 56.99,50.41 U11.AF27 ; v2(46.58,58.41) U23.C3
  SIG_L5 w0.094: v2(46.58,58.41) 46.61,58.38 v2(46.61,56.23)
DDR1_D10: length 21.5
  TOP w0.12: U11.AG27 v2(56.98,51.21) ; v2(48.18,58.41) U23.A3
  INT_L3 w0.094: v2(56.98,51.21) 56.63,51.56 55.88,51.56 55.64,51.81 55.64,52.31 53.06,54.89 52.94,54.89 52.41,54.36 52.29,54.36 52.21,54.44 52.21,54.56 52.74,55.09 52.74,55.21 52.66,55.29 52.55,55.29 52.03,54.77 51.91,54.77 51.83,54.85 51.83,54.97 52.35,55.49 52.35,55.6 52.26,55.69 52.15,55.69 51.63,55.17 51.51,55.17 51.43,55.25 51.43,55.37 51.95,55.89 51.95,56 51.86,56.09 51.75,56.09 51.23,55.57 51.11,55.57 51.03,55.65 51.03,55.77 51.55,56.28 51.55,56.4 51.47,56.48 51.35,56.48 50.83,55.97 50.71,55.97 50.63,56.05 50.63,56.17 51.15,56.68 51.15,56.8 50.99,56.96 50.86,56.96 50.55,56.64 50.42,56.64 48.65,58.41 v2(48.18,58.41)
DDR1_D11: length 21.7
  TOP w0.12: v2(45.91,56.23) 46.3,55.84 48.98,55.84 49.91,56.77 50.08,56.77 50.19,56.66 50.19,56.24 50.29,56.13 50.44,56.13 50.55,56.24 50.55,56.66 50.65,56.77 50.8,56.77 50.91,56.66 50.91,56.24 51.01,56.13 51.16,56.13 51.26,56.24 51.26,56.66 51.37,56.77 51.52,56.77 51.62,56.66 51.62,56.24 51.73,56.13 53.34,56.13 53.47,56.01 53.47,52.68 56.15,50.01 U11.AF28 ; v2(46.58,53.61) U23.C8
  SIG_L5 w0.094: v2(46.58,53.61) 46.58,55.56 v2(45.91,56.23)
DDR1_D12: length 21.6
  TOP w0.12: U11.AE26 v2(57.79,49.61) ; v2(47.38,53.61) U23.B8
  BOTTOM w0.12: v2(47.38,53.61) 47.37,53.62 47.37,54.86 47.62,55.12 48.81,55.12 48.91,55.01 48.91,54.46 49.02,54.36 49.17,54.36 49.27,54.46 49.27,55.01 49.38,55.12 49.52,55.12 49.63,55.01 49.63,54.46 49.74,54.36 49.88,54.36 49.99,54.46 49.99,55.01 50.1,55.12 51.05,55.12 51.26,54.91 51.26,54.76 51.16,54.66 51.16,54.51 51.26,54.4 51.41,54.4 51.51,54.51 51.66,54.51 51.77,54.4 51.77,54.25 51.66,54.15 51.66,54 51.77,53.89 51.92,53.89 52.02,54 52.17,54 52.28,53.89 52.28,53.75 52.17,53.64 52.17,53.49 52.28,53.39 52.43,53.39 52.53,53.49 52.68,53.49 52.79,53.39 52.79,53.24 52.68,53.13 52.68,52.98 52.79,52.88 52.94,52.88 53.04,52.98 53.19,52.98 53.85,52.32 53.85,49.66 54.36,49.15 57.02,49.15 57.48,49.61 v2(57.79,49.61)
DDR1_D13: length 21.7
  TOP w0.12: v2(48.18,59.21) U23.A2 ; U11.AC25 v2(58.59,48.01)
  SIG_L5 w0.094: v2(48.18,59.21) 48.16,59.21 47.75,58.8 47.75,57.96 47.83,57.88 47.92,57.88 48.01,57.8 48.01,57.68 47.92,57.6 47.83,57.6 47.75,57.52 47.75,57.4 47.83,57.32 47.92,57.32 48.01,57.24 48.01,57.12 47.92,57.04 47.83,57.04 47.75,56.95 47.75,56.84 47.83,56.75 47.92,56.75 48.01,56.67 48.01,56.55 47.92,56.47 47.83,56.47 47.75,56.39 47.75,55.37 48.77,54.36 v2(48.77,53.21)
  SIG_L10 w0.094: v2(48.77,53.21) 48.77,51.44 51.82,48.39 58.2,48.39 v2(58.59,48.01)
DDR1_D14: length 21.4
  TOP w0.12: v2(46.58,59.21) U23.C2 ; U11.AC24 v2(59.39,48.01)
  INT_L3 w0.094: v2(59.39,48.01) 58.96,48.43 56.22,48.43 47.62,57.02 46.36,57.02 45.34,58.04 45.34,58.52 45.62,58.81 U23.C2 v2(46.58,59.21)
DDR1_D15: length 21.4
  TOP w0.12: v2(48.18,54.41) U23.A7 ; U11.AD25 v2(58.59,48.81)
  BOTTOM w0.12: v2(48.18,54.41) 48.63,53.96 49.69,53.96 49.8,53.86 49.8,53.53 49.92,53.41 50.12,53.41 50.59,53.88 50.76,53.88 50.88,53.76 50.88,53.61 50.46,53.19 50.46,53.04 50.57,52.94 50.72,52.94 51.14,53.36 51.29,53.36 51.39,53.26 51.39,53.11 50.97,52.68 50.97,52.53 51.08,52.43 51.22,52.43 51.65,52.85 51.8,52.85 51.9,52.75 51.9,52.6 51.48,52.18 51.48,52.03 51.58,51.92 51.73,51.92 52.16,52.34 52.3,52.34 52.41,52.24 52.41,52.09 51.99,51.67 51.99,51.52 52.09,51.41 52.24,51.41 52.66,51.83 52.81,51.83 53.34,51.31 53.34,49.4 53.98,48.77 57.15,48.77 57.59,49.21 58.24,49.21 58.59,48.86 v2(58.59,48.81)
DDR1_D16: length 25
  TOP w0.12: v2(44.18,47.21) U24.E3 ; U11.V20 v2(62.59,44.01)
  INT_L3 w0.094: v2(44.18,47.21) 43.65,47.21 43.43,46.99 43.43,45.85 45.47,43.81 48.26,43.81 49.4,42.67 55.25,42.67 55.89,42.03 60.34,42.03 60.56,42.25 60.56,42.52 60.83,42.78 61.14,42.78 61.41,43.05 61.41,43.36 61.63,43.58 61.94,43.58 62.36,44.01 v2(62.59,44.01)
DDR1_D17: length 24.7
  TOP w0.12: U11.W20 v2(62.59,44.81) ; v2(42.58,42.41) U24.H8
  INT_L3 w0.094: v2(62.59,44.81) 62.99,44.4 62.99,43.88 62.7,43.58 62.43,43.58 62.16,43.32 62.16,43.05 61.9,42.78 61.63,42.78 61.36,42.52 61.36,42.25 61.1,41.98 60.83,41.98 60.61,41.76 60.61,41.49 60.34,41.23 55.8,41.23 54.99,42.04 42.95,42.04 v2(42.58,42.41)
DDR1_D18: length 24.9
  TOP w0.12: U24.F8 43.82,42.81 44.18,43.17 44.18,44.18 45.09,45.09 48.34,45.09 48.44,44.99 49.05,44.99 50.42,46.35 50.42,49.53 50.67,49.78 51.05,49.78 51.35,49.49 51.35,49.34 50.99,48.98 50.99,48.83 51.1,48.72 51.25,48.72 51.61,49.08 51.76,49.08 51.86,48.98 51.86,48.83 51.5,48.47 51.5,48.32 51.61,48.21 51.76,48.21 52.12,48.57 52.26,48.57 52.37,48.47 52.37,48.32 52.01,47.96 52.01,47.81 52.12,47.71 52.26,47.71 52.62,48.07 52.77,48.07 52.88,47.96 52.88,47.81 52.52,47.45 52.52,47.3 52.62,47.2 52.77,47.2 53.13,47.56 53.28,47.56 53.39,47.45 53.39,47.3 53.15,47.07 53.15,46.92 53.27,46.81 U11.AB28
DDR1_D19: length 25.2
  TOP w0.12: U11.AC28 55.14,47.61 51.49,51.25 47.82,51.25 47.62,51.05 47.62,50.42 47.82,50.23 49.34,50.23 49.53,50.04 49.53,46.74 48.51,45.72 44.3,45.72 U24.H7
DDR1_D20: length 24.8
  TOP w0.12: U11.AC27 v2(56.99,48.01) ; v2(42.58,47.21) U24.H3
  BOTTOM w0.12: v2(42.58,47.21) 43.05,46.74 43.05,46.23 43.18,46.1 43.43,46.1 43.53,46.21 43.53,46.38 43.64,46.48 43.79,46.48 43.89,46.38 43.89,46.21 44,46.1 44.15,46.1 44.25,46.21 44.25,46.38 44.36,46.48 44.51,46.48 44.61,46.38 44.61,46.21 44.72,46.1 44.87,46.1 44.97,46.21 44.97,46.38 45.08,46.48 45.23,46.48 45.33,46.38 45.33,46.21 45.44,46.1 45.58,46.1 45.69,46.21 45.69,46.38 45.8,46.48 45.94,46.48 46.05,46.38 46.05,46.21 46.16,46.1 47.88,46.1 48.77,46.99 48.77,50.8 48.89,50.93 52.71,50.93 52.83,50.81 52.83,49.02 53.47,48.39 56.6,48.39 v2(56.99,48.01)
DDR1_D21: length 24.9
  TOP w0.12: U11.Y19 v2(63.39,45.61) ; v2(43.38,48.01) U24.G2
  INT_L3 w0.094: v2(43.38,48.01) 43.78,47.61 44.35,47.61 47.76,44.2 48.51,44.2 49.53,43.18 55.5,43.18 55.88,42.8 60.31,42.8 60.56,43.05 60.56,43.32 60.88,43.63 61.14,43.63 61.36,43.85 61.36,44.12 61.63,44.38 61.63,44.38 61.68,44.43 61.99,44.43 62.21,44.65 62.21,44.96 62.48,45.23 63.01,45.23 v2(63.39,45.61)
DDR1_D22: length 25.2
  TOP w0.12: U24.F7 43.81,43.64 43.81,44.58 44.58,45.34 48.77,45.34 49.91,46.48 49.91,50.68 50.03,50.8 51.44,50.8 51.68,50.55 51.68,50.4 51.45,50.17 51.45,50.02 51.56,49.92 51.71,49.92 51.94,50.15 52.09,50.15 52.26,49.97 52.26,49.82 52.03,49.59 52.03,49.44 52.13,49.34 52.28,49.34 52.52,49.57 52.66,49.57 52.77,49.46 52.77,49.32 52.54,49.08 52.54,48.94 52.64,48.83 52.79,48.83 53.02,49.06 53.17,49.06 53.28,48.96 53.28,48.81 53.05,48.58 53.05,48.43 53.15,48.32 53.3,48.32 53.53,48.55 53.68,48.55 53.79,48.45 53.79,48.3 53.56,48.07 53.56,47.92 53.66,47.81 54.42,47.81 55.03,47.21 56.99,47.21 U11.AB27
DDR1_D23: length 24.9
  TOP w0.12: U11.Y20 v2(62.59,45.61) ; v2(44.18,48.01) U24.F2
  INT_L3 w0.094: v2(62.59,45.61) 62.36,45.61 61.97,45.21 61.61,45.21 59.98,43.58 55.89,43.58 55.8,43.66 55.8,43.73 55.72,43.81 55.6,43.81 55.52,43.73 55.52,43.66 55.44,43.58 55.32,43.58 55.24,43.66 55.24,43.73 55.16,43.81 55.04,43.81 54.96,43.73 54.96,43.66 54.88,43.58 54.76,43.58 54.68,43.66 54.68,43.73 54.59,43.81 54.48,43.81 54.39,43.73 54.39,43.66 54.31,43.58 54.2,43.58 54.11,43.66 54.11,43.73 54.03,43.81 53.91,43.81 53.83,43.73 53.83,43.66 53.75,43.58 53.63,43.58 53.55,43.66 53.55,43.73 53.47,43.81 53.35,43.81 53.27,43.73 53.27,43.66 53.18,43.58 53.07,43.58 52.98,43.66 52.98,43.73 52.9,43.81 52.79,43.81 52.7,43.73 52.7,43.66 52.62,43.58 52.5,43.58 52.42,43.66 52.42,43.73 52.34,43.81 52.22,43.81 52.14,43.73 52.14,43.66 52.06,43.58 51.94,43.58 51.86,43.66 51.86,43.73 51.77,43.81 51.66,43.81 51.58,43.73 51.58,43.66 51.49,43.58 51.38,43.58 51.29,43.66 51.29,43.73 51.21,43.81 51.09,43.81 51.01,43.73 51.01,43.66 50.93,43.58 50.81,43.58 50.73,43.66 50.73,43.73 50.65,43.81 50.53,43.81 50.45,43.73 50.45,43.66 50.36,43.58 50.14,43.58 49.15,44.58 47.85,44.58 44.42,48.01 v2(44.18,48.01)
DDR1_D24: length 19.4
  TOP w0.12: U11.AA23 v2(60.19,46.41) ; v2(49.78,44.58) 48.39,44.58 48.26,44.7 46.48,44.7 U24.D7
  INT_L3 w0.094: v2(49.78,44.58) 49.98,44.38 60.3,44.38 61.36,45.45 61.36,45.82 61.09,46.1 60.49,46.1 v2(60.19,46.41)
DDR1_D25: length 19.4
  TOP w0.12: U11.Y22 v2(60.99,45.61) ; v2(46.58,47.21) U24.C3
  INT_L3 w0.094: v2(46.58,47.21) 47.05,46.74 48.77,46.74 49.02,46.99 49.02,48.77 49.28,49.02 52.07,49.02 55.86,45.23 60.61,45.23 v2(60.99,45.61)
DDR1_D26: length 19.3
  TOP w0.12: U11.Y23 v2(60.19,45.61) ; v2(48.18,47.21) U24.A3
  INT_L3 w0.094: v2(60.19,45.61) 59.81,45.98 59.06,45.98 58.67,45.59 56.01,45.59 50.42,51.18 48.89,51.18 48.58,50.87 48.58,47.61 v2(48.18,47.21)
DDR1_D27: length 19.5
  TOP w0.12: U11.AA24 v2(59.39,46.41) ; v2(47.38,42.41) U24.B8
  BOTTOM w0.12: v2(59.39,46.41) 59.36,46.41 58.96,46.01 56.82,46.01 56.59,46.24 56.59,46.54 55.88,47.24 51.82,47.24 51.63,47.43 51.63,48.01 51.38,48.26 50.28,48.26 50.04,48.01 50.04,46.48 48.51,44.96 47.49,44.96 47.37,44.84 47.37,42.42 v2(47.38,42.41)
DDR1_D28: length 19
  TOP w0.12: U11.Y24 v2(59.39,45.61) ; v2(48.18,43.21) U24.A7
  BOTTOM w0.12: v2(59.39,45.61) 58.99,45.21 56.9,45.21 56.26,45.85 56.26,46.23 55.63,46.86 51.31,46.86 51.18,46.99 51.18,47.51 51.06,47.62 50.54,47.62 50.42,47.51 50.42,42.93 50.16,42.67 49.28,42.67 48.74,43.21 v2(48.18,43.21)
DDR1_D29: length 19.3
  TOP w0.12: v2(46.58,42.41) U24.C8 ; U11.AA26 v2(57.79,46.41)
  BOTTOM w0.12: v2(46.58,42.41) 46.56,42.43 46.56,45.16 46.74,45.34 48.26,45.34 49.66,46.74 49.66,48.64 49.91,48.9 51.82,48.9 52.07,48.64 52.07,47.76 52.19,47.64 56.12,47.64 56.64,47.12 57.07,47.12 v2(57.79,46.41)
DDR1_D30: length 19.4
  TOP w0.12: U11.AA25 v2(58.59,46.41) ; v2(48.18,48.01) U24.A2
  INT_L3 w0.094: v2(48.18,48.01) 47.8,48.39 47.24,48.39 46.99,48.64 46.99,51.18 47.37,51.56 50.55,51.56 56.13,45.98 58.16,45.98 v2(58.59,46.41)
DDR1_D31: length 19.2
  TOP w0.12: v2(46.58,48.01) U24.C2 ; U11.AA28 52.1,46.01 51.6,45.51 51.6,44.07 52.2,43.48 52.2,42.29 51.69,41.78 50.04,41.78 49.53,42.29 49.53,43.69 v2(49.15,44.07)
  SIG_L5 w0.094: v2(49.15,44.07) 46.99,46.23 46.99,47.6 v2(46.58,48.01)
DDR1_DQM0: length 23.6
  TOP w0.12: U11.AD23 v2(60.19,48.81) ; v2(44.98,54.41) U23.E7
  SIG_L10 w0.094: v2(44.98,54.41) 44.58,54 44.58,52.45 44.7,52.32 47.5,52.32 47.75,52.58 47.75,53.72 48.01,53.98 48.89,53.98 49.15,53.72 49.15,51.69 51.69,49.15 59.84,49.15 v2(60.19,48.81)
DDR1_DQM1: length 21.5
  TOP w0.12: v2(45.78,58.41) U23.D3 ; U11.AB23 v2(60.19,47.21)
  INT_L3 w0.094: v2(60.19,47.21) 60.58,47.6 60.58,48.26 60.33,48.51 59.94,48.51 59.68,48.78 59.68,49.03 59.44,49.28 56.26,49.28 48.01,57.53 46.66,57.53 v2(45.78,58.41)
DDR1_DQM2: length 24.9
  TOP w0.12: U11.AC26 v2(57.79,48.01) ; v2(44.98,43.21) U24.E7
  BOTTOM w0.12: v2(44.98,43.21) 43.56,44.63 43.56,45.47 43.81,45.72 48.13,45.72 49.15,46.74 49.15,50.42 49.28,50.55 52.33,50.55 52.45,50.43 52.45,48.77 53.21,48.01 56.38,48.01 56.9,47.5 57.28,47.5 v2(57.79,48.01)
DDR1_DQM3: length 19
  TOP w0.12: U11.AA27 v2(56.99,46.41) ; v2(45.78,47.21) U24.D3
  INT_L3 w0.094: v2(45.78,47.21) 46.23,47.65 46.23,51.69 46.48,51.94 50.67,51.94 56.21,46.41 v2(56.99,46.41)
DDR1_DQS0: length 24
  TOP w0.102: U23.F3 43.78,58.24 43.68,58.34 43.48,58.34 43.38,58.24 43.38,57.84 43.57,57.65 48.13,57.65 50.55,60.07 53.46,60.07 55.37,58.16 55.37,54.36 56.18,53.55 57.83,53.55 58.95,52.43 58.95,51.64 U11.AH25
DDR1_DQS1: length 21.2
  TOP w0.102: U23.C7 46.22,54.84 46.22,55.21 46.53,55.52 48.37,55.52 48.51,55.37 49.02,55.37 49.57,54.82 49.57,53.92 49.67,53.82 49.88,53.82 49.98,53.92 49.98,55.06 50.29,55.37 50.78,55.37 51.09,55.06 51.09,53.92 51.2,53.82 51.4,53.82 51.5,53.92 51.5,55.18 51.82,55.5 52.51,55.5 52.82,55.19 52.82,52.46 55.68,49.6 57,49.6 U11.AE27
DDR1_DQS2: length 25
  TOP w0.102: U11.AD27 56.98,48.81 54.99,48.81 51.86,51.94 46.74,51.94 46.36,51.56 46.36,49.79 46.72,49.43 48.62,49.43 48.77,49.28 48.77,47.11 48.07,46.41 43.79,46.41 43.69,46.52 43.69,46.71 U24.F3
DDR1_DQS3: length 19.3
  TOP w0.102: U11.Y28 56.53,45.26 52.4,45.26 52.3,45.16 52.3,44.53 52.4,44.42 53.36,44.42 53.82,43.96 53.82,42.27 52.6,41.05 49.5,41.05 48.76,41.79 48.76,43.18 47.95,44 47.62,44 47.39,43.77 47.39,43.46 47.13,43.2 46.59,43.2 U24.C7
DDR1_DQS_ECC: length 3.5
  TOP w0.12: U11.V27 v2(56.99,44.01)
  BOTTOM w0.12: v2(56.99,44.01) 56.59,43.61 56.02,43.61 55.75,43.34 55.75,42.83 R274.1
